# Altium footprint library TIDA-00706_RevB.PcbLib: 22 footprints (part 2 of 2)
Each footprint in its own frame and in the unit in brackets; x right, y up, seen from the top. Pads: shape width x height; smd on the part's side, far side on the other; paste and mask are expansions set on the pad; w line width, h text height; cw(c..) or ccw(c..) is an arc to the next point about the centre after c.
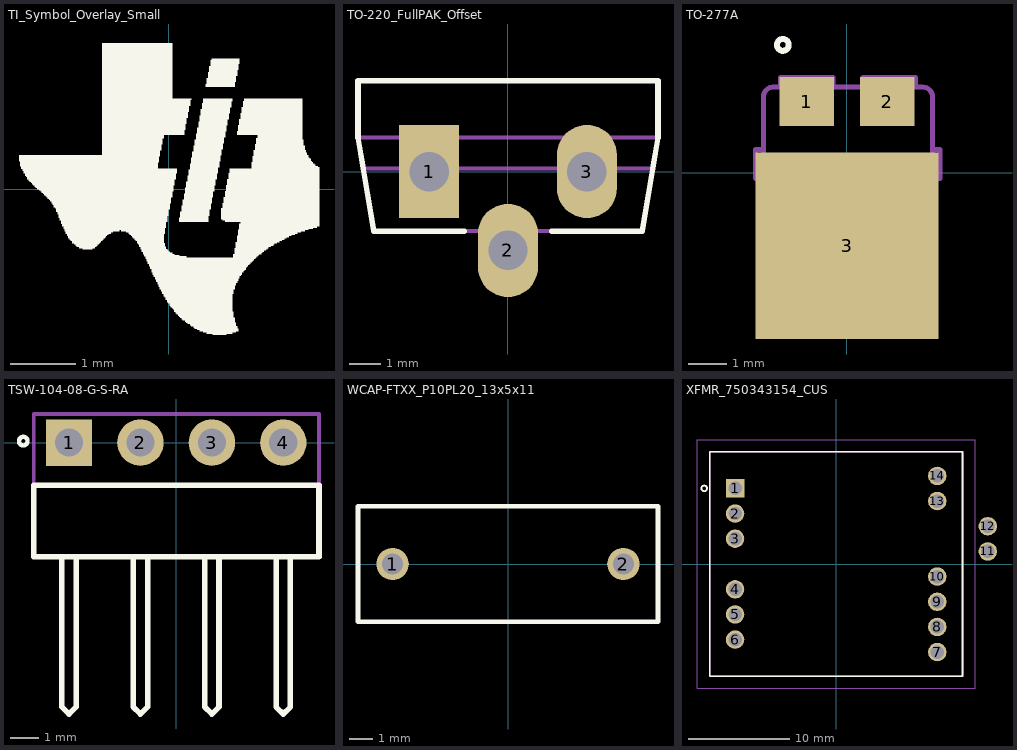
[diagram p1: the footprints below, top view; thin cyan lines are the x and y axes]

## TI_Symbol_Overlay_Small [mm]
Top Overlay:
  drawing of 3 lines, arcs and shapes, not listed

## TO-220_FullPAK_Offset [mm] "Infineon  PG-TO220-3-31"
height 19.4
pads (3):
  rect 1.93x3 hole 1.27: 1(-2.54,0)
  oval 1.93x3 hole 1.27: 2(0,-2.54) 3(2.54,0)
Top Overlay:
  lines w0.178: -4.655,0.095 -4.825,1.095 ; -4.325,-1.915 -1.4,-1.915 ; -4.325,-1.915 -4.825,1.085 -4.825,1.095 ; 1.4,-1.915 4.325,-1.915 4.825,1.085 4.825,1.095 ; 4.655,0.095 4.825,1.095 ; -4.825,1.095 -4.825,2.915 4.825,2.915 4.825,1.095
Mechanical 5:
  lines w0.127: -0.89,-1.915 -0.89,-2.058 -0.89,-2.853 0.89,-2.853 0.89,-1.915 ; -4.825,1.095 -4.825,1.085 -4.325,-1.915 4.325,-1.915 4.825,1.085 4.825,1.095 ; -4.825,1.095 -4.825,2.915 4.825,2.915 4.825,1.095 ; -4.825,1.095 4.825,1.095 ; -4.825,1.095 -4.655,0.095 4.655,0.095 4.825,1.095
  text ".Designator" at -1.219,-1.219 h0.76
3D body: height 22.91, standoff -3.95, extent -4.825,-2.845 4.825,2.915

## TO-277A [mm] "Vishay"
height 1.2
pads (3):
  rect 1.4x1.27 smd: 1(-1.04,1.83) 2(1.04,1.83)
  rect 4.72x4.8 smd: 3(0,-1.883)
Top Overlay:
  circle w0.152: c-1.651,3.286 r0.152
Mechanical 5:
  lines w0.127: -2.15,-0.15 -2.35,-0.15 -2.35,0.6 -2.15,0.6 ; -1.715,2.2 -1.715,2.45 -0.365,2.45 -0.365,2.2 ; -1.075,-3.95 -1.075,-4.2 1.125,-4.2 1.125,-3.95 ; 0.415,2.2 0.415,2.45 1.765,2.45 1.765,2.2 ; 2.2,-0.15 2.4,-0.15 2.4,0.6 2.2,0.6 ; -2.15,-3.7 ccw(c-1.9,-3.7) -1.9,-3.95 1.95,-3.95 ccw(c1.95,-3.7) 2.2,-3.7 2.2,1.95 ccw(c1.95,1.95) 1.95,2.2 -1.9,2.2 ccw(c-1.9,1.95) -2.15,1.95 -2.15,-3.7
  text ".Designator" at -0.787,-0.346 h0.76
3D body: height 1.2, standoff 0, extent -2.35,-4.2 2.4,2.45

## TSW-104-08-G-S-RA [mm] "Samtec Right Angle Header"
height 2.794
pads (4):
  rect 1.65x1.65 hole 1: 1(-3.81,0)
  round 1.65 hole 1: 2(-1.27,0) 3(1.27,0) 4(3.81,0)
Top Overlay:
  circle w0.152: c-5.436,0.051 r0.152
  lines w0.2: -4.064,-4.064 -4.064,-9.398 -3.81,-9.652 -3.556,-9.398 -3.556,-4.064 ; -1.524,-4.064 -1.524,-9.398 -1.27,-9.652 -1.016,-9.398 -1.016,-4.064 ; 1.016,-4.064 1.016,-9.398 1.27,-9.652 1.524,-9.398 1.524,-4.064 ; 3.556,-4.064 3.556,-9.398 3.81,-9.652 4.064,-9.398 4.064,-4.064 ; -5.06,-4.064 5.08,-4.064 5.08,-1.524 -5.06,-1.524 -5.06,-4.064
Mechanical 5:
  lines w0.127: -4.064,-4.064 -4.064,-9.398 -3.81,-9.652 -3.556,-9.398 -3.556,-4.064 ; -1.524,-4.064 -1.524,-9.398 -1.27,-9.652 -1.016,-9.398 ; 1.016,-4.064 1.016,-9.398 1.27,-9.652 1.524,-9.398 ; 3.556,-4.064 3.556,-9.398 3.81,-9.652 4.064,-9.398 ; -1.016,-9.398 -1.016,-4.064 -1.016,-9.398 ; 1.524,-9.398 1.524,-4.064 1.524,-9.398 ; 4.064,-9.398 4.064,-4.064 4.064,-9.398 ; -5.06,-4.064 -5.06,1.016 5.08,1.016 5.08,-4.064 -5.06,-4.064
  text ".Designator" at -0.864,-2.007 h0.76
3D body: height 3.05, standoff -2.29, extent -5.08,-9.906 5.08,0.318

## WCAP-FTXX_P10PL20_13x5x11 [mm] "TH, 2-Leads, Body 13x5mm, Pitch 10mm"
height 11.5
pads (2):
  round 1.4 hole 0.9: 1(-5,0) 2(5,0)
Top Overlay:
  lines w0.2: -6.5,-2.5 6.5,-2.5 6.5,2.5 -6.5,2.5 -6.5,-2.5
Mechanical 5:
  lines w0.1: -6.5,-2.5 -6.5,2.5 6.5,2.5 6.5,-2.5 -6.5,-2.5
  text ".Designator" at -0.61,-0.686 h0.76
3D body: height 11, standoff -20, extent -6.5,-2.5 6.5,2.5

## XFMR_750343154_CUS [mm] "TRANSFORMER, 2.49 MM PITCH, 14-PIN, 16 MM HEIGHT"
height 16
pads (14):
  rect 1.82x1.82 / inner round 1.82 / far side rect 1.82x1.82 hole 1.32: 1(-10,7.48)
  round 1.82 hole 1.32: 2(-10,4.99) 3(-10,2.5) 4(-10,-2.5) 5(-10,-4.99) 6(-10,-7.48) 7(10,-8.715) 8(10,-6.225) 9(10,-3.735) 10(10,-1.245) 11(15,1.245) 12(15,3.735) 13(10,6.225) 14(10,8.715)
Top Overlay:
  circle w0.178: c-13.058,7.48 r0.279
  lines w0.178: -12.5,-11.1 12.5,-11.1 12.5,11.1 -12.5,11.1 -12.5,-11.1
Mechanical 5:
  circle w0.127: c-10,7.48 r0.279
  lines w0.127: -12.5,-11.1 12.5,-11.1 12.5,11.1 -12.5,11.1 -12.5,-11.1
  text ".Designator" at -1.524,-0.508 h0.76
Mechanical 15:
  lines w0.05: -13.77,-12.27 -13.77,12.27 13.77,12.27 13.77,-12.27 -13.77,-12.27
Mechanical 17:
  text "LEAD LENGTH:3MM" at -6.477,7.239 h1.02
3D body: height 16, standoff 0, extent -12.5,-11.1 12.5,11.1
